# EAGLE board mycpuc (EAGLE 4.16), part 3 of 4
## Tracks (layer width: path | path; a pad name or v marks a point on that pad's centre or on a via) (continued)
GND  (via drill 0.3 pad 0.76, 0.3 pad 0.81) (continued)
  Top 0.203: LED3.C 85.96,2.92 85.95,2.91 85.95,1.91 | LED4.C 81.96,1.92 81.95,1.91 | LED5.C 78.01,1.92 78,1.91 | LED6.C 74.01,1.92 74,1.91 | IC7.22 20.06,47.7 19.25,48.51 18.65,48.51 v18.05,49.11 | 92.93,41.16 92.3,41.16 92.15,41.31 90,41.31 89.55,41.76 87.05,41.76 | IC8.22 22.39,58.72 22.55,58.56 27.4,58.56 28.15,59.31 28.15,60.36 27.85,60.66 27.05,60.66 26.5,61.21 25.95,61.21 25.55,61.61 C63.2
  Top 0.254: LED10.C 55.01,2.1 55.2,1.91 | LED7.C 67.01,1.92 67,1.91 | LED8.C 63.01,1.92 63,1.91 | LED9.C 59.01,1.92 59,1.91 | 15.8,20.53 IC6.11 | IC6.12 15,19.86 15.8,19.86 | 10.4,58.91 10.4,58.9 J1.C20 | IC6.13 20.85,19.76 | IC9.2 16.93,37.34 18,38.41 | 18,38.41 v18,38.46 | IC9.22 19.72,36.69 18,38.41 | IC9.11 15.87,31.49 16,31.36 16,30.84 | 16,41.85 16,42.31 15.81,42.5 IC7.11 | IC7.2 16.09,48.35 16.85,49.11 v18.05,49.11 | 120.45,13.11 120.47,13.09 IC19.8 | IC19.13 115.39,17.62 117,16.01 119.4,16.01 120.45,14.96 v120.45,14.71 | 104.85,14.96 v104.8,15.31 104,16.11 103.1,16.11 102.55,15.56 102.55,14.66 102.95,14.26 102.95,12.96 102.94,12.97 IC18.6 | IC20.13 81.33,17.18 83.75,14.76 v85.85,14.76 | 15.05,59.36 15.04,59.37 IC8.2 | 115.55,28.86 115.56,28.85 C76.2 | R60.2 122.92,15.83 v121.8,14.71 | v139.45,80.16 139.4,80.16 | v139.45,80.16 IC13.12 | v139.45,80.16 139.45,80.21 140.15,79.51 IC13.11 | IC13.13 v136.45,80.16 | IC13.22 137.05,74.31 139.1,72.26 139.1,72.06 139.15,72.01 v139.15,72.06 | IC21.P142 62.25,52.91 62.8,52.36 v62.8,52.41 63.3,52.41 63.75,52.86 IC21.P139 | v65.1,50.96 65.05,50.96 65.1,51.16 65.1,52.66 65.25,52.81 IC21.P136 | IC21.P117 74.75,52.11 v75.75,51.11 76.1,51.11 76.6,51.61 76.6,52.76 76.25,53.11 IC21.P114 | IC21.P9 v60.59,47.75 v60.6,47.76 | IC21.P16 v60.59,44.25 v60.6,44.26 | v60.6,41.26 60.6,41.31 60.54,41.25 IC21.P22 | IC21.P29 v60.59,37.75 v60.6,37.76 | v79.4,38.26 79.4,38.31 79.46,38.25 IC21.P81 | v79.4,41.76 79.35,41.76 79.36,41.75 IC21.P88 87.05,41.76 | IC21.P101 v79.41,48.25 v79.4,48.26 | IC21.P94 v79.41,44.75 v79.4,44.76 | IC21.P39 62.25,33.76 v62,34.01 | 61.75,33.76 IC21.P38
  Top 0.254: v62,34.01 61.75,33.76 | 61.25,33.76 IC21.P37 | 61.75,33.76 61.25,33.76 | IC21.P45 65.25,34.96 v65.3,35.01 65.25,35.06 | IC21.P42 63.75,33.01 62.75,34.01 v62,34.01 | v74.8,35.06 74.8,35.01 74.75,34.96 IC21.P64 | IC21.P67 76.25,32.86 77.4,34.01 v77.55,34.01 | 61.25,33.76 v60.85,33.76 | 87.05,41.76 87.1,41.76 IC14.22 87.07,41.76 87.05,41.76 | IC14.11 92.32,46.99 92.05,47.26 92.05,47.64 | 92.93,41.16 IC14.2 | J3.1 138.81,86.1 138.75,86.16 | 133.8,87.66 133.76,87.7 SW2.2 | 147.6,49.8 J5.15 147.62,49.88 | 106.85,97.06 106.86,97.05 LED1.C 106.96,97.05 107,97.01 108.5,97.01 | v107,93.26 106.95,93.31 107.8,93.31 108.5,94.01 108.5,97.01 | 108.5,97.01 109.8,98.31 113.3,98.31 v114.55,97.06 114.55,97.01 114.6,97.06 LED11.C | C16.- 78.36,72.26 78.35,72.41 78.61,72.43 R113.1 | 88.08,61.61 88.1,61.61 C12.2 | 147.62,49.88 147.65,49.91 | R119.2 145.45,47.71 147.62,49.88 | R118.2 144.17,54.03 143.8,53.66 143.8,50.41 144.25,49.96 C73.2 | R132.2 v136.14,19.5 v136.15,19.51 | v118.8,59.66 118.8,59.71 118.85,59.66 | v118.8,56.61 118.8,56.66 | 115.25,47.41 v115.2,47.46 | 109.25,47.41 v109.4,47.46 | 105.8,49.66 v106.1,49.91 | IC23.100 106.53,60.99 106.5,60.91 | v114.55,59.91 114.53,59.93 | v118.8,53.16
  Top 0.3: IC8.2 11.76,59.37 11.3,58.91 10.45,58.91 10.4,58.91
  Top 0.305: 16,52.87 16,53.36 15.84,53.52 IC8.11 | IC5.10 83.25,70.36 v82.9,70.41 82.7,70.41 82.6,70.31 IC5.11 IC5.15 | 81.95,63.31 IC5.3 | 81.95,64.06 81.95,64.56 82.6,65.21 | C73.2 147.5,49.96 147.62,49.84 J5.15 147.62,49.79 147.65,49.76 147.6,49.71 147.6,47.41 C74.2 | 118.85,59.66 IC23.75 | 118.8,56.66 IC23.69 | v118.8,53.16 IC23.62 | IC23.44 115.53,47.14 115.25,47.41 | IC23.31 109.03,47.18 109.25,47.41 | IC23.21 105.8,49.66 | v107.3,59.66 106.5,60.46 106.5,60.91 | 114.53,59.93 IC23.84
  Top 0.406: 55.2,1.91 57,1.91 | 57,1.91 59,1.91 63,1.91 67,1.91 74,1.91 78,1.91 81.95,1.91 85.95,1.91 | 15.8,20.53 15.8,19.86 15.8,19.11 15.1,18.41 15.1,16.11 v15.05,16.11 | 70.7,14.76 70.68,14.78 C88.2 | 57.3,18.51 57.3,19.64 Q2.2 | 50.21,18.82 v50.25,18.86 | 18,28.86 v18,27.51 | v18,30.21 18,28.86 | 18,28.86 C54.2 | 18,28.86 C53.2 | 20.85,19.76 20.85,19.21 v20.5,18.86 | v18,38.46 18,39.91 | 18,39.91 v18,41.31 18,41.36 | 18,39.91 C59.2 | 18,39.91 C60.2 | IC9.12 16,30.84 17.37,30.84 v18,30.21 | v18,30.21 18,30.26 18.58,30.84 IC9.13 | IC7.12 16,41.85 16.01,41.85 16.5,41.36 18,41.36 | IC7.13 19.99,41.85 19.5,41.36 18,41.36 | v18.05,49.11 18.05,50.91 | 18.05,50.91 v18.05,52.31 | 18.05,50.91 C55.2 | 18.05,50.91 C56.2 | IC8.12 16,52.87 17.49,52.87 v18.05,52.31 | v18.05,52.31 18.05,52.36 18.56,52.87 IC8.13 | C92.2 75.81,16.75 75.85,16.71 75.75,16.61 v75.75,15.31 | C90.2 95.52,15.84 96.6,14.76 v96.75,14.76 96.7,14.76 96.6,14.66 96.6,13.11 96.58,13.09 IC18.1 | v109.7,15.21 109.5,15.41 109.5,16.51 109.49,16.52 C91.2 | v104.8,15.31 104.8,14.76 105.45,14.11 105.45,13.01 IC18.8 | IC20.8 86.41,14.71 86.45,14.76 v85.85,14.76 v86.8,14.76 | 115.55,30.26 v115,30.26 | 115.55,30.26 v116,30.26 | 115.55,28.86 115.55,30.26 | C76.2 115.55,28.63 115.55,28.46 113.7,28.46 C79.2 | 57,1.91 v57,2.81 | C84.2 85.45,10.06 v85.1,9.71 | IC14.13 89.02,47.64 v89.15,47.61 | IC14.12 92.05,47.64 92.03,47.64 v92,47.61 | C72.2 90.88,37.78 v91.3,37.38 91.42,37.31 91.66,37.08 C93.2 | 138.75,86.16 138.75,86.81 137.9,87.66 133.8,87.66 | R13.1 54.33,85.48 53.2,86.61 50.8,86.61 50.8,86.6 C6.- | 67.98,87.03 67.95,87.06 67.99,87.1 R11.1 67.97,87.18 67.95,87.16
  Top 0.406: v67.45,80.46 v68.4,80.46 68.4,81.46 67.65,82.41 67.6,82.36 66.5,81.46 v66.5,80.46 v67.45,80.46 | v67.45,80.46 67.45,82.16 | IC5.15 82.6,65.21 82.22,64.78 C11.2 | 80.9,63.61 80.9,66.91 84.3,66.91 84.3,63.61 80.9,63.61 | 80.9,63.61 81.95,63.61 81.95,63.31 | J1.A1 | IC11.10 29.59,94.02 v29.57,94.01 | v31,88.61 31.02,88.61 30.86,88.44 IC11.28 | IC10.10 29.49,80.47 29.49,80.45 29.45,80.41 29.45,79.71 28.98,79.23 v28.98,78.61 | v31.38,72.83 31.35,72.63 30.86,72.14 IC10.28 | 25.53,61.58 | C63.2 25.53,61.58 | 25.53,61.58 C64.2 | 25.53,61.58 25.55,61.56 | 36.9,29.31 37,29.31 38.35,30.66 39.6,30.66 v39.7,30.56
  Top 0.6: C63.2 25.78,62.59 26.25,63.06 v26.3,63.06
  Top 0.61: v72.15,14.76 70.7,14.76 | Q1.2 65.25,19.71 66.25,20.71 v67.75,20.71 | 57.3,18.51 58.42,18.51 v59.23,17.71 | C89.2 50.21,18.82 | 120.45,13.11 v120.45,14.71 v121.8,14.71 | v76.4,70.71 76.4,71.06 | v82.9,70.41 82.95,65.06 81.95,64.06 81.95,63.31 | v23.1,30.46 28.8,30.46 29.95,29.31 36.9,29.31
  Top 0.813: 46.55,86.86 J4.59 | C6.- 50.47,86.86 46.55,86.86 | 67.98,87.03 C7.2 67.98,82.74 67.6,82.36 67.64,82.31 C2.- | C5.2 60.1,87.21 60.1,88.25 60.64,88.8 60.65,88.81 67.35,88.81 67.95,88.21 67.95,87.16 | 75.2,87.81 v75.9,87.81 75.9,82.96 75.2,82.96 75.2,87.81 | 74,87.81 v73.8,87.81 73.45,87.81 | 74,87.81 74.75,87.81 | 74.75,87.81 v74.85,87.81 | 73.45,87.81 v72.7,87.81 72.7,86.91 | 73.45,87.81 73.44,87.79 C15.- 73.42,85.83 73,85.36 | 73,82.86 72.42,82.33 C14.- 72.42,82.43 72.55,82.56 72.77,82.34 C13.- | v75.45,70.71 v76.4,70.71 | v82.9,70.41 v83.8,70.41 | 74.75,87.81 75.2,87.81 | 74.75,87.81 74.75,82.96 74,82.96 | 74,82.96 73.95,83.21 | 74,87.81 74,82.96 | 44,86.86 46.55,86.86 | 10.4,13.21 10.4,13.2 J1.C2 | 14.87,13.21 C17.- | 10.4,89.38 10.4,89.41 | 7.45,89.38 7.45,89.36 | C18.- | v100.95,28.06 100.95,28.46 100.96,28.47 | v100.95,27.06 v100.95,28.06 | v100.95,28.06 v100.95,29.06
  Top 1.016: 76.4,71.06 77,71.66 77.7,71.66 78.36,72.31 C16.- | C10.- 88.07,58.88 88.1,58.91 88.08,58.93 88.08,61.61 C9.- 82.83,64.53 82.85,64.61 82.75,65.41 IC5.15 | 10.4,13.21 14.87,13.21 | J1.A1 5.35,13.21 10.45,13.21 10.45,10.66 J1.A1
  Top 1.27: J1.A32 7.45,89.38 | 7.45,89.38 10.4,89.38 | 7.45,89.38 C18.- | 100.96,28.47 100.97,28.46 102.85,28.46 D20.A | v38.75,10.81 38.12,10.11 39.48,10.11 38.75,9.21 D21.A | v38.75,10.81 v39.75,10.81 | v38.75,10.81 v37.75,10.81 | J1.A20 10.45,58.91
  Top 1.676: 73,82.86 73,85.36
  Route2 0.406: 65.1,93.71 65.1,89.91 | 65.1,93.71 65.1,94.61 | 63.5,99.21 66.75,99.21 | 65.1,93.71 62.3,93.71 61.65,93.06 59.25,93.06 58.05,94.26
  Route2 1.93: 43.75,58.91 47.05,58.91
  Bottom 0.203: T5.2 122.05,83.06 122.05,83.76 122.3,84.01 124.9,84.01 | T2.2 134.05,83.76 133.8,84.01 130.1,84.01 | v31.38,72.83 31.4,72.81 31.47,72.88 31.32,72.88 | v28.98,78.61 29,78.61 28.92,78.64 28.93,78.59 | v29.57,94.01 29.6,94.01 29.62,93.98 29.57,93.98
  Bottom 0.254: 10.45,58.91 10.45,58.9 J1.C20 | v115,30.26 115,30.21 114.91,30.3 | C81.2 89.46,15.47 89.45,15.46 89.4,15.51 | v85.85,14.76 v86.8,14.76 | R66.2 68.4,12 68.4,12.86 69.05,13.51 70.9,13.51 v72.15,14.76 | 53.89,21.87 v53.85,21.96 | 54,15.01 53.95,15.06 | T2.2 | T4.2 130.04,84.01 130.1,84.01 129.45,84.66 v129.45,86.66 | T3.2 126.05,83.76 125.8,84.01 124.9,84.01 v124.9,86.66 | v129.5,94.21 129.5,94.16 129.07,94.59 IC2.1 | v114.55,97.06 114.5,97.06 v114.56,97.05 C1.2 | v107,93.26 106.9,93.21 106.98,93.29 | 14.49,71.52 R24.1 14.47,69.19 14.48,69.18 | 14.49,71.52 R25.1 14.49,73.77 14.5,73.76 14.51,73.77 R26.1 14.51,76.02 14.5,76.01 14.48,76.03 R27.1 14.48,80.04 14.5,80.11 v14.5,80.06 13.85,80.06 13,80.91 C52.2 | 14.49,71.52 14.5,71.51 | 14.48,69.18 14.5,69.16 | 14.48,69.18 R22.1 14.48,66.94 | 14.48,66.94 14.5,66.96 R23.1 14.5,64.71 14.51,64.72 R21.1 14.51,62.55 14.53,62.53 | 14.48,66.94 14.45,66.91 | 14.53,62.53 14.55,62.51 | R17.2 14.53,62.53 | 14.55,62.56 14.55,62.41 14.85,62.11 15.35,62.11 v16.15,61.36 | v15.05,95.01 14.5,95.01 13.65,94.16 R39.2 | C8.2 82.89,66.75 82.9,67.21 v82.9,70.41 | T1.2 41.72,89.89 44,87.56 44,86.76 44.01,86.77 J4.60 | IC12.47 35.88,66.08 v35.65,66.31 35.38,66.14 IC12.46 | IC12.27 25.88,63.48 v26.3,63.06 | R114.2 41.38,55.89 41.65,56.16 41.65,57.06 43.5,58.91 43.95,58.91 43.96,58.9 J4.38 | 116.9,34.01 116.89,34.32 C75.2 | 58.05,94.26 J2.3 | 107.4,76.26 107.42,76.28 J15.16
  Bottom 0.305: v109.53,54.28 109.55,54.33 108.84,54.31 C100.1 | D26.C 106.57,85.69 108.7,83.56 108.7,77.46 107.5,76.26 107.48,76.28 J15.16
  Bottom 0.35: IC16.25 89.6,9.8 89.67,9.81 91.05,9.81 v91.35,9.51
  Bottom 0.406: 10.45,58.91 11.3,58.91 11.95,58.26 12.6,58.26 | 12.6,58.26 C57.2 | C58.2 17.65,58.21 17.6,58.26 12.6,58.26 | 114.91,30.3 IC15.25 | v115,30.26 v116,30.26 116,30.41 116.9,31.31 116.9,34.01 | 89.4,15.51 87.55,15.51 v86.8,14.76 87.83,13.73 C80.2 | v140.4,68.31 140.15,68.06 139.05,68.06 139.03,68.04 C70.2 | v139.15,72.06 139.15,72.01 139.17,71.99 C69.2 139.15,70.46 139.2,70.46 139.2,69.36 138.95,69.11 138.95,68.11 | C41.2 69.45,48.61 69.42,48.64 | C45.2 | 72.89,48.62 C40.2 | C36.2 77,49.36 77.02,49.34 | C37.2 63.67,47.54 63.64,47.57 | 69.65,37.46 69.67,37.44 C43.2 | 71.43,37.43 71.45,37.41 | 71.43,37.43 C39.2 | C39.2 71.43,37.43 | C44.2 73.15,37.46 73.14,37.45 | 64.11,36.57 64.1,36.56 | 64.11,36.57 C34.2 | 64.14,36.6 64.11,36.57 | 77.25,36.56 76.97,36.58 C32.2 | 77.25,38.26 C31.2 | 72.65,38.81 v72.6,38.86 | 63.6,50.96 v65.1,50.96 | 62.9,52.36 62.95,52.41 v62.8,52.41 62.91,52.52 | 77.55,36.41 77.3,36.66 | v65.3,35.01 64.9,35.01 64.25,35.66 | v62,34.01 62.05,34.01 62.05,34.06 | C50.2 | C3.2 69.55,45.31 69.5,45.36 | C20.2 72.44,54.35 73,54.91 v73,55.61 73,55.66 | C27.2 60.95,54.41 | C27.2 | 61.14,54.22 C27.2 | 77.21,54.15 77.2,54.16 77.22,54.18 C21.2 77.25,54.16 77.6,53.81 | C33.2 64.14,38.45 64.15,38.46 | 61,38.46 61,40.86 | 79.39,45.12 79.4,45.11 | C22.2 77.4,31.66 | C22.2 77.55,31.81 | 78.92,31.78 C30.2 | C22.2 77.55,31.81 | 77.55,31.81 77.7,31.81 77.7,31.78 | 77.55,34.06 v77.55,34.01 | C23.2 66.94,30.17 v66.95,30.11 | 54,17.06 C47.2 | 54,17.06 54.04,17.1 C49.2 53.9,19.01 53.9,21.86 53.89,21.87 | C48.2 53.95,15.06 54,15.11 54,17.06 | 54.8,12.31 v54.75,12.36 54,13.11 54,15.01 | v61.85,11.01 61.85,11.06 62.55,11.06 63.94,12.45 IC1.11
  Bottom 0.406: v89.15,47.61 89.85,47.61 | C71.2 89.85,43.71 89.85,47.61 | 89.85,47.61 v92,47.61 | 146.3,96.66 146.29,96.67 C87.2 | C85.2 106.67,93.59 107.05,93.21 106.98,93.29 | 50.31,87.17 50.3,87.16 | IC4.1 50.31,87.17 | 50.31,87.17 50.34,87.2 | v107.3,59.66 107.5,59.66 107.95,59.21 107.95,58.26 C95.1 | C96.1 114.42,58.51 114.55,58.58 v114.55,59.91 | C97.1 117.1,52.91 117.35,53.16 v118.8,53.16 | C101.1 116.95,48.01 116.69,47.88 115.17,47.88 v115.2,47.46 115.15,47.56 115.15,48.81 114.9,49.16 C98.1 | C99.1 108.92,46.81 109.38,47.26 109.38,47.44 v109.4,47.46 | Q3.GND 120.72,61.49 120.7,61.46 | 120.7,61.46 v120.7,60.81 | 120.7,61.46 120.36,61.77 IC24.4 118.81,61.77 118.8,61.76 | C103.1 116.33,62.88 117.45,61.76 118.8,61.76 | v118.8,59.66 118.8,61.76 | v29.57,94.01 29.57,93.98 29.25,93.71 C65.2 | v31,88.61 30.95,88.63 31.55,89.23 C66.2 | C67.2 27.95,77.31 27.95,78.21 28.33,78.59 28.93,78.59 | 31.32,72.88 31.32,72.89 31.35,72.81 31.07,73.09 31.07,74.89 31.65,75.31 C68.2
  Bottom 0.61: C46.2 69.42,48.64 | C41.2 C45.2 | C45.2 72.89,48.62 | C35.2 77.02,49.34 | 63.64,47.57 C38.2 | C42.2 69.65,37.46 | C43.2 C39.2 | C39.2 73.14,37.45 | C33.2 64.14,36.6 | 77.25,36.56 77.25,38.26 78.55,38.26 | 67.6,48.61 v67.6,47.26 v68.85,47.26 69.5,46.61 69.5,45.36 | v72.6,47.26 72.6,48.61 | 67.65,37.46 v67.65,38.86 | 72.65,37.46 72.65,38.81 | 63.6,49.21 63.6,50.96 | 62.9,52.36 62.9,51.61 63.65,50.86 | v60.6,47.76 63.7,47.76 | v75.75,51.11 76.25,51.11 77,50.36 77,49.41 | v79.4,48.26 79,48.26 78.35,47.61 | 78.35,47.61 77,47.61 | 78.35,47.61 79.4,46.56 79.4,45.11 v79.4,44.76 | 77.55,36.41 77.55,34.06 77.55,31.81 | 78.55,38.26 79.35,38.26 | v79.4,41.76 78.55,40.91 78.55,38.26 | 64.25,36.46 64.25,35.66 63.85,35.26 63.25,35.26 62.05,34.06 | v60.6,37.76 60.6,38.06 61,38.46 64.15,38.46 | 60.8,33.76 61.1,34.01 v62,34.01 62.31,33.7 C24.2 | v67.65,38.86 C50.2 | v67.65,38.86 v68.85,38.86 | 61.14,54.22 C19.2 62.91,52.52 | 77.21,54.15 C28.2 | 77.6,53.81 77.6,52.61 v77.8,52.41 | C26.2 61,40.86 v60.6,41.26 | C29.2 79.39,45.12 | 77.7,31.78 78.92,31.78 | C25.2 60.47,33.38 v60.85,33.76 | J9.4 146.3,96.66 | 67.5,80.51 v67.45,80.46 67.4,80.41 67.95,80.41 67.95,71.81 | 67.95,71.81 67.93,71.83 C61.2 67.62,71.83 67.65,71.86 67.7,71.81 67.95,71.81 | 67.95,71.81 C62.2 | C104.2 56.98,95.33 J2.3
  Bottom 0.813: 50.34,87.2 C4.2 | J4.59 46.55,86.86 | 49.91,86.86 IC4.1 | v68.4,80.46 v66.5,80.46
  Bottom 1.27: 46.55,86.86 49.91,86.86 | J15.18 104.9,76.3 104.9,76.31 107.45,76.31
  other vias: 75.85,67.31 79.65,64.91 77.6,67.31 69.2,71.76
  pour Route2 (isolate 0.254): 0.35,99.71 0.35,0.31 159.75,0.31 159.75,99.71 65.3,99.71 65.3,66.51 56.05,66.51 49.55,73.06 49.55,89.86 64.9,89.86 64.9,99.71
  pour Bottom (isolate 0.254): 62.95,55.66 80.25,55.66 80.9,55.01 80.9,31.76 80.25,31.11 77.25,31.11 75.25,33.11 64.8,33.11 62.8,31.11 60.15,31.11 59.35,31.91 59.35,54.46 59.65,54.76 62.05,54.76
  pour Top (isolate 0.305, no thermals): 80.95,63.11 86.95,63.11 86.95,57.66 89.25,57.66 89.25,67.26 83.25,67.26 83.25,67.81 75.4,67.81 75.4,63.61 80.45,63.61
  pour Bottom: 69.55,82.01 65.45,82.01 65.45,68.36 72.4,68.36 72.4,73.21 71.2,74.41 71.2,80.36
  pour Top (no thermals): 66.25,83.41 66.25,86.56 58.3,86.56 58.3,90.31 68.85,90.31 68.85,83.41
IN0
  Top 0.254: IC18.2 97.9,12.91 98,12.9 98,11.9 100.35,9.56 101.7,9.56 103.15,8.11 103.12,7.78 J10.4
  Bottom 0.203: 103.05,9.71 R95.2
  Bottom 0.254: J10.4 103.12,9.64 R95.2
IN1
  Top 0.254: IC18.3 99.12,11.78 100.75,10.16 103.35,10.16 105.7,7.81 105.69,7.8 J10.6
  Bottom 0.203: R96.2 105.66,9.7 105.65,9.71
  Bottom 0.254: J10.6 105.66,9.7
IN2
  Top 0.254: IC18.4 100.39,11.76 101.4,10.76 105.25,10.76 J10.8
  Bottom 0.203: 108.2,9.66 R97.2
  Bottom 0.254: R97.2 | J10.8 108.2,9.66
IN3
  Top 0.254: IC18.5 101.67,11.74 102.05,11.36 106.45,11.36 110.04,7.77 | 110.04,7.77 110.75,7.76 | 110.04,7.77 J10.10
  Bottom 0.203: R98.2 110.74,9.7 110.75,9.71
  Bottom 0.254: J10.10 110.74,9.7
IN4
  Top 0.254: IC18.10 104.2,17 104.9,16.31 105.45,16.31 105.75,16.01 105.75,14.96 106.45,14.26 106.45,12.31 109.25,9.51 111.55,9.51 113.28,7.78 | 113.28,7.78 113.3,7.76 | 113.28,7.78 J10.12
  Bottom 0.203: R99.2
  Bottom 0.254: J10.12 113.28,9.63 R99.2
IN5
  Top 0.254: IC18.11 102.94,20.44 103.15,20.66 106.2,20.66 106.5,20.36 106.5,15.16 107.15,14.51 107.15,12.56 109.5,10.16 113.5,10.16 115.85,7.81 115.84,7.8 J10.14
  Bottom 0.203: R100.2 115.79,9.7 115.8,9.71 115.82,9.69
  Bottom 0.254: J10.14 115.82,9.69
IN6
  Top 0.254: IC18.12 101.67,20.47 102.45,21.26 106.65,21.26 107.15,20.76 107.15,15.51 107.85,14.81 107.85,12.86 109.9,10.76 115.45,10.76 118.4,7.81 118.39,7.8 J10.16
  Bottom 0.203: 118.36,9.65 R101.2
  Bottom 0.254: 118.36,9.65 118.4,9.61 118.36,9.57 J10.16
IN7
  Top 0.254: IC18.14 99.12,20.53 100.45,21.86 106.95,21.86 107.85,20.96 107.85,15.76 108.55,15.06 108.55,13.11 110.25,11.36 117.35,11.36 J10.18 | J10.18 120.95,7.76 | J10.18
  Bottom 0.203: R102.2
  Bottom 0.254: R102.2 120.9,9.61 J10.18
INTRES  (via drill 0.3 pad 0.76)
  Top 0.203: J4.54 43.99,79.22
  Top 0.254: J4.54 44.04,79.22 45.25,78.01 47.4,78.01 48.15,77.26 48.15,71.46 51.05,68.56 64.45,68.56 73.75,59.26 IC21.P119 | 43.99,79.22 42.65,80.56 42.65,91.11 v42.1,91.66
  Bottom 0.203: 42.15,91.66 v42.1,91.66 40.9,91.66 40.69,91.65 T1.1
  Bottom 0.254: T1.1 40.59,91.87 40.55,91.91 40.58,91.94 R115.1
INTRQ
  Top 0.254: J12.31 136.21,55.07 137.45,56.31 139.85,56.31 141,55.16 | 141,55.16 J13.31 | 141,55.16 142.8,55.16 143.55,55.91 145.5,55.91 145.48,55.93 R118.1
IO_LOAD
  Top 0.254: IC21.P97 85.04,46.25 85.15,46.36 87.1,46.36 IC14.15
IO_OUT1
  Top 0.254: IC21.P96 83.01,45.75 83.05,45.71 87.08,45.71 IC14.16
IO_OUT2
  Top 0.254: IC21.P95 82.96,45.25 83.15,45.06 87.1,45.06 IC14.17
IOCLK  (via drill 0.3 pad 0.81)
  Top 0.203: IC14.10 92.12,46.34 90.7,47.76 v90.7,48.56
  Top 0.254: v103.55,15.11 103.55,14.86 103.5,14.81 104.2,14.1 IC18.7 | IC19.11 117.92,17.28 v117.95,17.26 | IC20.11 83.9,19 v83.9,17.21
  Route15 0.254: v91.05,33.01 91.05,33.31 92.9,35.16 92.9,37.81 90.62,40.11 90.62,43.86 89.88,44.61 89.88,47.73 v90.7,48.56
  Bottom 0.254: v117.95,17.26 116.95,16.26 113.7,16.26 113.05,16.91 111.9,16.91 111.3,16.31 104.4,16.31 103.55,15.46 v103.55,15.11 103.55,15.06 102.35,13.86 96.35,13.86 93,17.21 87.95,17.21 86.85,16.11 84.8,16.11 83.9,17.01 v83.9,17.21 75.9,17.21 72.6,20.51 72.6,23.21 74.7,25.31 83,25.31 85,27.31 85.9,27.31 91,32.41 91,33.01 v91.05,33.01
IOEN1
  Top 0.254: IC9.3 12.47,36.69 11.85,37.31 4.35,37.31 3.9,37.76 3.9,74.81 4.5,75.41 7.05,75.41 8.3,76.66 10.4,76.66 10.42,76.68 J1.C27
IOEN2
  Top 0.203: 12.53,36.04 11.5,35.01 4.25,35.01 3.15,36.11
  Top 0.254: 12.53,36.04 IC9.4 | 3.15,36.11 3.15,75.51 4.4,76.71 5.3,76.71 5.32,76.68 J1.A27
IOEN3
  Top 0.203: 12.83,35.39 12,34.56 3.52,34.56 2.4,35.68
  Top 0.254: 12.83,35.39 IC9.5 | J1.A28 5.34,79.17 4.12,79.16 2.38,77.41 2.4,35.68
IOIN  (via drill 0.3 pad 0.81)
  Top 0.254: IC21.P98 84.14,46.75 v84.45,47.06 | v93.6,23.96 93.6,24.01 93.3,24.31 93.3,28.21 89.15,32.36 v89.15,33.01 | v73.85,64.26 73.45,64.26 65.65,72.06 55.15,72.06 53.55,73.66 v49.85,73.66
  Route15 0.254: v98.45,24.01 v98.45,17.21
  Bottom 0.203: 27.4,56.81 23.1,61.11 20.85,61.11 19.49,62.47
  Bottom 0.254: R111.1 98.52,17.21 v98.45,17.21 | v89.15,33.01 86.95,35.21 86.95,41.16 84.45,43.66 v84.45,47.06 83.95,47.56 83.95,62.11 82,64.06 74.05,64.06 v73.85,64.26 | v98.45,24.01 98.45,24.06 98.35,23.96 v93.6,23.96 | v49.85,73.66 51.15,73.66 52.55,72.26 52.55,69.61 50.25,67.31 50.25,60.46 47.4,57.61 43.25,57.61 42.55,56.91 42.55,55.11 41.75,54.31 37.7,54.31 35.2,56.81 27.4,56.81 | D1.2 19.49,62.47
IOLOAD  (via drill 0.3 pad 0.81)
  Top 0.203: v90.8,46.51 91.05,46.51 91.82,45.74 93.42,45.74 93.45,45.71 IC14.9
  Top 0.254: IC19.12 116.66,20.4 116.45,20.61 109.15,20.61 107.25,22.51 102,22.51 | 102,22.51 99.9,22.51 97.9,20.51 97.9,19.21 97.85,19.16 97.86,19.15 IC18.15 97.86,18.01 97.55,17.71 97.55,16.61 v97,16.06 | IC20.12 82.59,17.11 83.4,16.31 85.75,16.31 v86.45,17.01 | 102,22.51 v102,24.01
  Route15 0.254: v90.8,46.51 91.2,46.51 95.33,42.38 95.33,34.83 v93.5,33.01
  Bottom 0.254: v97,16.06 95.3,16.06 93.5,17.86 87.25,17.86 86.5,17.11 86.5,17.01 86.45,17.06 v86.45,17.01 | v102,24.01 99.5,26.51 99.5,28.56 98.9,29.16 98.1,29.16 94.25,33.01 v93.5,33.01
IOOUT1  (via drill 0.3 pad 0.81)
  Top 0.203: IC14.8 92.27,45.04 92.1,45.21 91.5,45.21 91.35,45.36 v90.8,45.36
  Top 0.254: IC19.14 114.11,17.26 v114.15,17.26 | v124,15.01 124.45,15.46 124.45,22.26 119.6,27.11 119.6,30.06 114.55,35.11 108.8,35.11 v108.7,35.16
  Bottom 0.254: v124,15.01 123.95,15.01 120.55,18.41 117.05,18.41 115.9,17.26 v114.15,17.26 | v108.7,35.16 108.7,35.11 105.85,32.26 99.65,32.26 96.05,35.86 96.05,41.36 92.05,45.36 v90.8,45.36
IOOUT2  (via drill 0.3 pad 0.81)
  Top 0.254: IC20.14 80.06,20.2 79.25,21.01 v75,21.01 | IC14.7 91.57,44.39 v91.6,44.41
  Route15 0.254: v92.25,33.01 92.25,32.98 92.28,33.23 93.55,34.48 93.55,42.83 91.95,44.41 v91.6,44.41
  Bottom 0.254: v75,21.01 73.95,21.01 73.35,21.61 73.35,22.91 75.15,24.71 83.35,24.71 85.3,26.66 86.25,26.66 92.25,32.66 v92.25,33.01
IORD  (via drill 0.3 pad 0.81)
  Top 0.254: IC21.P113 76.75,55.51 75.9,56.36 75.9,59.91 65.15,70.66 54.55,70.66 52.75,72.46 51.15,72.46 50.75,72.06 50.75,70.96 51.4,70.31 v51.65,70.31
  Bottom 0.254: J4.40 45.3,60.16 47.1,60.16 49.5,62.56 49.5,68.16 v51.65,70.31
IORDY
  Top 0.254: 130.9,48.76 126,48.76 124.6,50.16 IC23.56 | 130.9,48.76 130.9,50.01 | IC23.56 120.5,50.16 | IC23.56 | J13.27 139.69,48.76 130.9,48.76 | 130.9,50.01 J12.27 | R120.1 130.93,50.04 130.9,50.01
IOWR
  Top 0.254: R94.2 77.39,58.02 77.4,58.01 77.25,57.86 IC21.P112
IOWR_R  (via drill 0.3 pad 0.81)
  Top 0.254: R94.1 77.39,60.82 77,61.21 75.55,61.21 65.4,71.36 54.85,71.36 53.15,73.06 50.65,73.06 v49.85,72.26
  Bottom 0.254: v49.85,72.26 48,70.41 48,63.51 47.15,62.66 45.95,62.66 44.65,63.96 J4.42
IRQ  (via drill 0.3 pad 0.81)
  Top 0.254: R36.2 16.55,62.51 17.05,62.01 v17.35,62.01 | IC21.P130 68.25,56.86 64.05,61.06 52.65,61.06 v51.3,62.41
  Route2 0.254: v16.65,82.91 15.95,82.21 15.95,63.41 v17.35,62.01
  Bottom 0.203: 19.7,61.06 20.2,60.56 22.8,60.56 27.25,56.06
  Bottom 0.254: v51.3,62.41 51.3,56.41 47.35,52.46 38.35,52.46 34.75,56.06 27.25,56.06 | v17.35,62.01 18.3,61.06 19.7,61.06 | D6.1 17.93,82.83 17.85,82.91 v16.65,82.91
IRQ1
  Top 0.254: R29.1 11.75,64.71 11.15,65.31 8.2,65.31 7,66.51 5.3,66.51 5.32,66.52 J1.A23
  Bottom 0.254: R21.2 11.67,64.74 11.15,65.26 8.25,65.26 7,66.51 5.35,66.51 J1.A23
IRQ2
  Top 0.254: J1.C24 10.44,69.06 10.45,69.06 10.45,68.51 11.95,67.01 R30.1
  Bottom 0.254: J1.C24 10.58,69.24 R22.2
IRQ3
  Top 0.254: R31.1 12.2,69.26 11.15,70.31 8.25,70.31 7,69.06 5.3,69.06 5.31,69.06 J1.A24
  Bottom 0.254: R23.2 12.65,67.01 12.42,67.24 11.62,67.24 11.1,67.76 8.3,67.76 7,69.06 5.3,69.06 5.31,69.06 J1.A24
IRQ4
  Top 0.254: 10.4,71.6 10.35,71.66 | 10.4,71.6 J1.C25 | R32.1 10.5,71.51 10.4,71.6
  Bottom 0.254: 10.4,71.6 10.35,71.66 | J1.C25 10.4,71.6 | R24.2 10.47,71.54 10.4,71.6
IRQ5
  Top 0.254: R33.1 11.95,73.76 11.1,72.91 8.35,72.91 7.05,71.61 5.3,71.61 5.3,71.6 J1.A25
  Bottom 0.254: R25.2 12.59,73.75 12.25,73.41 11.63,73.39 11.15,72.91 8.35,72.91 7.05,71.61 5.3,71.61 5.3,71.6 J1.A25
IRQ6
  Top 0.254: R34.1 12.95,76.01 11.05,74.11 10.5,74.11 10.45,74.16 10.44,74.14 J1.C26
  Bottom 0.254: R26.2 12.28,75.64 12.15,75.71 11.7,75.71 10.45,74.46 10.45,74.16 10.44,74.14 J1.C26
IRQ7
  Top 0.254: R35.1 12.45,78.26 12.05,77.86 12.05,76.41 11.1,75.46 8.3,75.46 7,74.16 5.3,74.16 5.31,74.14 J1.A26
  Bottom 0.254: R27.2 12.58,77.96 11.4,77.96 9.85,77.96 8.3,76.41 8.3,75.46 7,74.16 5.3,74.16 5.31,74.14 J1.A26
IRQIN  (via drill 0.3 pad 0.79)
  Top 0.254: v9.5,62.71 12.7,62.71 R36.1
  Bottom 0.254: 9.43,62.68 9.65,62.68 v9.5,62.71 | 9.43,62.68 v9.5,62.71 | v9.5,62.71 12.45,62.71 12.57,62.63 R17.1 | 9.43,62.68 9.45,62.71 6.75,60.01 6.75,39.76 10.45,36.06 10.44,36.04 J1.C11
IRQS1  (via drill 0.3 pad 0.81)
  Top 0.254: R29.2 16.65,64.71 v16.85,64.86 | IC21.P129 68.75,57.31 64.2,61.81 53.25,61.81 51.55,63.51 47.05,63.51 46.6,64.01 46.57,63.98 J4.41
  Bottom 0.254: v16.85,64.86 19.25,64.86 | 19.25,64.86 19.25,64.51 | 19.25,64.86 21.85,64.86 23.95,66.96 23.95,71.11 23.6,71.46 23.6,75.16 24.7,76.26 24.7,79.36 26.7,81.36 34.65,81.36 37.4,78.61 37.4,71.26 43.3,65.36 45.15,65.36 46.55,63.96 J4.41 | D1.1 19.24,64.7 19.25,64.86
IRQS2  (via drill 0.3 pad 0.81)
  Top 0.254: R30.2 v16.85,67.01 | IC21.P128 69.25,57.86 64.55,62.51 53.55,62.51 51.8,64.26 48.2,64.26 47.25,65.21 45.85,65.21 44.6,66.46 44,66.46 44.01,66.47 J4.44
  Bottom 0.254: v16.85,67.01 17.7,67.01 18.3,67.61 18.75,67.61 19,67.91 | 19,67.91 20.1,67.91 22.9,70.71 22.9,75.46 24.05,76.61 24.05,79.71 26.35,82.01 35,82.01 38.05,78.96 38.05,71.66 43.2,66.51 44.05,66.56 J4.44 | D2.2 19.04,67.62 19,67.91
IRQS3  (via drill 0.3 pad 0.81)
  Top 0.254: R31.2 15.9,69.26 v17,70.36 | IC21.P127 69.75,58.31 64.75,63.26 53.85,63.26 52.1,65.01 48.7,65.01 47.2,66.51 J4.43
  Bottom 0.254: v17,70.36 17.85,70.36 18.3,69.91 19.25,69.91 | 19.25,69.91 20.25,69.91 22.2,71.86 22.2,75.76 23.4,76.96 23.4,80.06 26,82.66 35.35,82.66 38.7,79.31 38.7,72.31 43.2,67.81 45.2,67.81 46.55,66.46 J4.43 | D2.1 19.24,69.9 19.25,69.91
IRQS4  (via drill 0.3 pad 0.81)
  Top 0.254: v17,71.71 16.8,71.51 R32.2 | IC21.P125 70.75,58.31 65.05,63.96 54.2,63.96 52.4,65.76 49.15,65.76 47.1,67.81 45.8,67.81 44.6,69.01 44.05,69.01 J4.46
  Bottom 0.254: v17,71.71 17.2,71.51 18.65,71.51 18.9,71.76 18.9,72.46 | 18.9,72.46 20.15,72.46 21.5,73.81 21.5,76.06 22.75,77.31 22.75,80.36 25.7,83.36 35.65,83.36 39.35,79.66 39.35,72.81 43.15,69.01 43.95,69.01 J4.46 | D3.2 19.2,72.4 18.9,72.46
IRQS5  (via drill 0.3 pad 0.81)
  Top 0.254: R33.2 16.15,73.76 17,74.61 v17,74.76 | IC21.P124 71.25,58.86 63.6,66.46 49.75,66.46 47.15,69.06 J4.45
  Bottom 0.254: v17,74.76 17.15,74.61 19.25,74.61 | 19.25,74.61 20.2,74.61 20.85,75.26 20.85,76.41 22.1,77.66 22.1,80.71 25.45,84.06 35.95,84.06 40,80.01 40,73.46 43.1,70.36 45.25,70.36 J4.45 | D3.1 19.25,74.42 19.25,74.61
IRQS6  (via drill 0.3 pad 0.81)
  Top 0.254: R34.2 15.4,76.11 v17,76.11 | IC21.P123 71.75,59.36 63.9,67.16 50.3,67.16 47.1,70.36 45.9,70.36 44.65,71.61 44.04,71.6 J4.48
  Bottom 0.254: v17,76.11 17.25,75.86 19,75.86 19.25,76.11 19.25,76.86 | 19.25,76.86 20.1,76.86 21.45,78.21 21.45,80.96 25.2,84.76 36.25,84.76 40.65,80.36 40.65,74.06 43.1,71.61 43.95,71.61 44,71.66 44.01,71.65 J4.48 | D4.2 19.25,76.81 19.25,76.86
IRQS7  (via drill 0.3 pad 0.81)
  Top 0.254: R35.2 16.2,78.26 17,79.06 v17,79.36 | IC21.P122 72.25,59.81 64.2,67.86 50.7,67.86 46.94,71.6 J4.47
  Bottom 0.254: v17,79.36 17.35,79.01 19.35,79.01 | 19.35,79.01 20.2,79.01 20.8,79.61 20.8,81.26 25,85.46 36.6,85.46 41.3,80.76 41.3,74.76 43.25,72.81 44.7,72.81 45.9,71.61 J4.47 | D4.1 19.35,79.01
LCD_D0
  Top 0.254: IC13.3 142.5,74.31 142.7,74.11 142.7,62.81 146.75,58.76 148.95,58.76 150.2,59.96 150.18,59.98 J5.8
  Bottom 0.254: J5.8 151.73,59.98 153,58.71 154.85,58.71 156,57.56 156,56.51 155.98,56.49 R85.2
LCD_D1
  Top 0.254: IC13.4 142.95,74.96 143.4,74.51 143.4,63.51 146.9,60.01 147.6,60.01 J5.7
  Bottom 0.254: J5.7 148.84,58.76 151.25,58.76 152.25,57.76 153.05,57.76 153.5,57.31 153.5,56.41 153.52,56.41 R86.2
LCD_D2
  Top 0.254: IC13.5 143.3,75.61 144.1,74.81 144.1,64.11 146.85,61.36 149,61.36 J5.6
  Bottom 0.254: R87.2 154,62.51 153.99,62.52 J5.6
LCD_D3
  Top 0.254: IC13.6 143.6,76.26 144.8,75.06 144.8,64.66 146.9,62.56 147.55,62.56 147.6,62.51 J5.5
  Bottom 0.254: J5.5 148.83,61.31 151.9,61.31 153.2,60.01 154.07,60.01 R88.2
LCD_D4
  Top 0.254: IC13.7 143.9,76.91 145.5,75.31 145.5,65.26 146.9,63.86 148.95,63.86 J5.4
  Bottom 0.254: R89.2 154.1,65.05 154.1,65.06 J5.4
LCD_D5
  Top 0.254: IC13.8 144.25,77.56 146.2,75.61 146.2,65.96 147.1,65.06 J5.3
  Bottom 0.254: J5.3 148.97,66.41 151.95,66.41 153.05,67.51 154.02,67.51 R90.2
LCD_D6
  Top 0.254: IC13.9 144.6,78.21 146.9,75.91 146.9,70.86 J5.2
  Bottom 0.254: R91.2 152.57,70.01 J5.2
LCD_D7
  Top 0.254: IC13.10 144.95,78.86 147.6,76.21 147.6,72.21 151.55,68.26 151.55,67.01 150.95,66.41 148.75,66.41 147.62,67.54 J5.1
  Bottom 0.203: R92.2 147.52,70.38
  Bottom 0.254: R92.2 147.6,70.36 147.62,70.34 J5.1
LCD_E1  (via drill 0.3 pad 0.81)
  Top 0.254: IC14.4 91.93,42.44 v91.6,42.11
  Bottom 0.254: v91.6,42.11 92.67,41.01 92.67,35.56 98.4,29.86 107.6,29.86 113.55,35.81 121.8,35.81 124.55,38.56 141.85,38.56 144.35,41.06 144.35,41.76 147.55,44.96 148.7,44.96 152.1,48.36 152.1,55.56 150.22,57.44 J5.10
LCD_E2  (via drill 0.3 pad 0.81)
  Top 0.254: IC14.3 94.62,41.79 94.95,41.46 94.95,39.86 94.6,39.51 v94.55,39.51
  Bottom 0.254: v94.55,39.51 94.85,39.51 95.4,38.96 95.4,35.61 99.4,31.66 106.55,31.66 112.5,37.61 120.65,37.61 125.75,42.71 125.75,44.26 127.75,46.26 141.9,46.26 146.35,50.71 146.35,56.16 J5.9
LCD_RS  (via drill 0.3 pad 0.81)
  Top 0.254: v91.6,43.26 91.75,43.26 92.23,43.74 IC14.6
  Bottom 0.254: v91.6,43.26 92,43.26 93.33,41.91 93.33,35.91 98.75,30.46 107.25,30.46 113.2,36.41 121.4,36.41 126.05,41.06 142.4,41.06 147.1,45.76 148.4,45.76 151.4,48.76 151.4,53.71 150.2,54.91 150.19,54.9 J5.12
LCD_RW  (via drill 0.3 pad 0.81)
  Top 0.254: IC14.5 95.07,43.09 95.6,42.56 95.6,39.11 94.75,38.26 v94.5,38.26
  Bottom 0.254: v94.5,38.26 94.5,35.61 99.1,31.06 106.9,31.06 112.85,37.01 121,37.01 127.6,43.61 143.65,43.61 148.9,48.86 148.9,53.71 147.62,54.88 J5.11
N$1  (via drill 0.3 pad 0.81)
  Top 0.254: SW2.1 119.87,95.61 v121.95,95.61
  Bottom 0.254: v121.95,95.61 121.95,96.46 | 121.95,96.46 121.95,97.56 122.55,98.16 131.7,98.16 141.3,88.46 141.3,86.06 141.31,86.05 J3.2 | R8.2 121.96,96.47 121.95,96.46
N$2  (via drill 0.3 pad 0.81)
  Top 0.254: IC21.P72 78.75,31.06 79.05,30.76 80.1,30.76 80.4,30.46 v80.45,30.46
  Route15 0.254: v57.05,8.66 57.02,8.66 59.48,11.11 v59.48,16.03
  Bottom 0.254: v80.45,30.46 80.3,30.61 78.35,30.61 78.2,30.46 76.55,30.46 75.5,29.41 73.7,29.41 73.3,29.81 71.5,29.81 68.65,26.96 59.85,26.96 59.4,26.51 59.4,19.91 | 59.4,19.91 IC1.3 | 59.4,19.91 59.4,19.08 60.17,18.31 60.17,16.73 v59.48,16.03 | v57.05,8.66 57.02,8.63 57.35,8.31 R155.1
N$3  (via drill 0.3 pad 0.81)
  Top 0.254: IC21.P71 78.25,30.56 79.05,29.76 v79.4,29.76
  Bottom 0.254: v79.4,29.76 76.8,29.76 75.8,28.76 73.15,28.76 68.4,24.01 68.4,23.01 67.15,21.76 65.95,21.76 | 63.94,19.92 IC1.10 63.95,19.91 63.94,19.92 | 63.94,19.92 63.94,19.9 63.9,19.86 | 65.95,21.76 65.95,22.81 R6.2 | 63.94,19.92 63.94,21.26 64.45,21.76 65.95,21.76
N$4  (via drill 0.3 pad 0.81)
  Top 0.254: IC21.P111 77.75,56.01 v78.15,56.41
  Bottom 0.254: R1.1 77.66,56.9 v78.15,56.41
N$5  (via drill 0.3 pad 0.81)
  Top 0.254: IC21.P110 78.25,55.26 v79.4,56.41
  Bottom 0.254: R2.1 77.41,58.95 79.4,56.96 79.4,56.46 79.35,56.41 v79.4,56.41
N$6
  Bottom 0.254: R7.1 127.99,96.47 R8.1 125.63,93.68 125.65,93.66 125.63,93.64 IC2.3 125.61,93.7 125.48,93.83 R10.2 121.12,93.83 120.35,93.81 120.35,95.16 119.5,96.01 C1.1
N$7
  Top 0.406: C7.1 66.08,87.08 66.05,87.11 66.09,87.15 R11.2 64.02,87.18 63.97,87.13 R12.1 63.9,87.16 63.79,87.05 IC3.1
N$8
  Bottom 0.254: R3.2 60.04,11.75 60.05,11.76 60.04,11.77 IC1.17
N$9  (via drill 0.3 pad 0.81)
  Top 0.254: IC21.P144 61.25,54.71 60.4,55.56 v60.4,55.76
  Bottom 0.254: v60.4,55.76 59.75,55.76 58.7,54.71 58.7,37.01 58,36.31 58,23.86 57.45,23.26 56.05,23.26 55.7,23.61 53.95,23.61 52.8,22.46 52.8,12.91 54.3,11.41 57.8,11.41 58.12,11.73 R3.1
N$10  (via drill 0.3 pad 0.81)
  Top 0.254: IC21.P143 61.75,55.71 v61.7,55.76 | v63.5,24.31 60.25,24.31 59.45,25.11 57.2,25.11 v57.15,25.16
  Bottom 0.254: IC1.7 61.99,19.95 62,19.96 62,21.41 61.59,21.82 R4.2 | R4.2 61.6,22.61 61.59,23.05 R4.2 | v61.7,55.76 61.7,56.16 61.2,56.66 59.75,56.66 58.1,55.01 58.1,37.31 57.4,36.61 57.4,25.41 v57.15,25.16 57.15,24.61 56.85,24.31 54.7,24.31 54.38,24.63 D22.1 | v63.5,24.31 63.5,23.46 62.7,22.66 R4.2 | D22.2 D22.1 | D22.1 54.45,25.51 54.5,25.46
N$11
  Top 0.254: L1.1 84.3,73.51 84.6,73.26 | 84.2,69.01 84.55,69.01
  Top 0.305: 84.55,69.01 IC5.8 | IC5.9 83.9,68.71 83.95,68.76
  Top 0.406: 83.95,68.76 84.2,69.01
  Top 1.016: 84.55,69.01 85.1,69.56 85.1,72.76 84.6,73.26
  pour Top (isolate 0.305, no thermals): 83.85,67.91 86.05,67.91 86.05,75.41 82.65,75.41 82.65,71.21 83.85,71.21
N$12  (via drill 0.3 pad 0.81)
  Top 0.254: v116.95,86.81 116.4,87.36 R9.2 | IC23.95 109.03,63.13 107.8,64.36 107.8,66.41 v107.95,66.56
  Route15 0.254: v116.95,86.81 116.35,86.21 116.35,70.46 115.05,69.16 110.55,69.16 v107.95,66.56
N$13  (via drill 0.3 pad 0.81)
  Top 0.254: v81.88,60.53 82.15,60.53 82.6,60.98 IC5.4
  Route15 0.254: v79.25,66.71 81.88,64.11 v81.88,60.53
  Bottom 0.254: v79.25,66.71 C8.1
N$15  (via drill 0.3 pad 0.81)
  Top 0.406: C6.+ 52.72,80.26 52.7,79.41 | R13.2 54.33,80.89 53.75,80.31 50.65,80.31 50.7,80.25
  Top 0.813: C6.+ 50.7,80.25 50.7,80.26 50.68,80.24 R16.1 | v52.7,78.46 v52.7,79.36 52.7,79.41
  Bottom 0.813: v52.7,78.46 v52.7,79.36 52.6,79.46 52.6,81.03 IC4.4 52.65,81.06 52.65,87.23 IC4.2
  other vias: 51.25,84.41 52.65,84.41 52.65,82.91 51.25,82.91 51.95,83.66
  pour Bottom (isolate 0.305, no thermals): 37.05,90.41 37.1,78.81 41.75,74.06 57,74.16 56.95,90.41
  pour Route15: 46.7,84.31 46.7,80.86 47.55,80.86 48.75,82.06 59.95,82.06 60.4,82.51 64,82.51 64,83.66 60.65,87.01 49.4,87.01
  pour Route2: 50.2,89.16 64.7,89.16 64.7,67.21 56.35,67.21 50.2,73.36
  pour Top (no thermals): 43.4,86.96 43.4,74.61 56.3,74.61 56.3,86.96
N$16  (via drill 0.3 pad 0.81)
  Top 0.254: IC6.22 19.77,25.73 19.4,25.36 19.4,18.51 20.05,17.86 21.6,17.86 21.8,18.06 v21.75,18.06
  Bottom 0.254: R18.1 21.77,18.08 v21.75,18.06
N$17
  Bottom 0.254: 18.15,91.36 C51.1 R40.2
N$18
  Bottom 0.254: R37.1 13.69,91.32 13.65,91.36 R39.1 D7.3
N$19
  Bottom 0.254: C104.1 58.91,96.55 59.25,96.21 | D25.3 60.75,96.21 60.6,96.06 | 60.6,94.26 60.59,94.27 J2.1
  Bottom 0.61: 60.75,96.21 59.25,96.21 | 60.6,96.06 60.6,94.26
N$20  (via drill 0.3 pad 0.81)
  Top 0.254: v34.67,94.03 34.67,94.01 IC11.6
  Bottom 0.203: 34.7,94.06 v34.67,94.03
  Bottom 0.254: R53.2 34.66,93.85 34.7,94.06
N$21  (via drill 0.3 pad 0.76)
  Route2 0.254: v26.25,53.21 26.15,53.31 26.15,60.46 27.15,61.46 v27.4,61.46
  Bottom 0.203: IC12.26 25.38,64.64 25.4,64.51
  Bottom 0.254: 25.4,64.51 25.4,62.66 26.6,61.46 v27.4,61.46 | v26.25,53.21 22.6,56.86 16.25,56.86 14.93,55.53 14.93,42.88 17.75,40.06 20.65,40.06 22.1,38.61 27.9,38.61 28.95,37.56 28.95,36.46 29.75,35.66 30.3,35.66 30.93,35.03 R54.2
N$22  (via drill 0.3 pad 0.76)
  Top 0.254: IC10.6 34.67,78.78 v34.9,78.56
  Bottom 0.254: 35.13,76.74 35.15,76.76 | R28.2 35.13,76.74 | 35.13,76.74 35.15,76.71 | 35.13,76.74 35.13,78.33 v34.9,78.56
N$23
  Top 0.254: 152.35,52.36 J5.14 | 152.35,52.36 152.35,72.46 143.1,81.71 132.6,81.71 128.55,85.76 111.9,85.76 110.95,86.71 R67.2 | 152.35,52.36 152.35,48.91 150.95,47.51 149.85,47.51 C74.1
N$24  (via drill 0.3 pad 0.81)
  Top 0.254: R55.2 113.48,26.43 113.52,26.43 113.55,26.46 114.45,26.46 115.1,27.11 v115.5,27.11
  Bottom 0.254: v115.5,27.11 115.3,27.11 114.59,26.4 IC15.19
N$25
  Bottom 0.254: C75.1 115.08,34.39 115.1,34.36 115.2,34.16
  Bottom 0.305: IC15.27 114.8,31.6 115.2,32.01 115.2,34.16
N$26  (via drill 0.3 pad 0.81)
  Top 0.254: C76.1 117.46,28.85 117.45,28.86 117.5,28.91 v117.5,30.11
  Top 0.305: D14.3 109.75,33.56 109.9,33.71 114.55,33.71 117.5,30.76 v117.5,30.11
  Bottom 0.254: IC15.3 118.34,30.95 v117.5,30.11
N$27
  Bottom 0.254: 110.92,26.24 111.3,26.26 | R56.2 110.92,26.24 | IC15.18 111.41,25.75 110.92,26.24
N$28  (via drill 0.3 pad 0.81)
  Top 0.254: C77.2 113.35,32.06 113.15,32.26 112.1,32.26 v111.8,32.56
  Bottom 0.254: IC15.28 112.11,32.25 v111.8,32.56
N$29  (via drill 0.3 pad 0.81)
  Top 0.254: C77.1 112.95,29.86 111.85,29.86 v111.7,29.71
  Bottom 0.254: v111.7,29.71 111.8,29.71 111.86,29.65 IC15.24
N$30
  Bottom 0.254: C78.2 122.7,32.76 122.25,32.3 120.7,32.31 120.64,32.25 IC15.1
N$31
  Bottom 0.254: IC15.2 121.25,31.61 121.31,31.55 124.14,31.55 124.4,31.81 124.4,32.56 124.35,32.76 C78.1
N$32  (via drill 0.3 pad 0.81)
  Top 0.254: v115.5,25.86 115.85,25.86 117,27.01 117.9,27.01 122.05,22.86 122.05,22.51 122.04,22.5 R57.2
  Bottom 0.254: IC15.17 114.64,25.1 115.4,25.86 v115.5,25.86
N$33
  Bottom 0.254: R58.2 111.38,24.29 111.55,24.45 IC15.16
N$34  (via drill 0.3 pad 0.81)
  Top 0.254: v115.55,24.46 115.67,24.39 R59.2
  Bottom 0.254: IC15.15 114.89,23.8 v115.55,24.46
N$35
  Top 0.254: R159.1 16.23,16.43 16.05,16.61 16.05,18.01 16.65,18.61 16.68,18.63 16.68,25.78 16.1,26.36 14.8,26.36 IC6.2
N$36
  Top 0.254: D9.3 104.08,25.34 105.25,26.51 107.8,26.51 107.96,26.67 D10.3 107.96,26.92 107.95,26.91 108,26.86 108.75,26.86 109.25,26.36 109.25,24.46 111.15,22.56 D8.3 114.29,21.87 114.9,21.26 117.3,21.26 117.55,21.01 122.25,21.01 122.95,20.31 122.95,19.46 R60.1
N$37
  Bottom 0.254: T2.1 135.94,83.85 136.35,84.26 136.35,86.71 137.75,88.11 137.75,90.76 137.15,91.36 131.55,91.36 131.05,90.86 131.05,90.01 131,89.96 R70.1
N$38
  Bottom 0.254: C80.1 91.34,11.7 90.75,11.11 89.6,11.11 89.59,11.09 IC16.27
N$39  (via drill 0.3 pad 0.81)
  Top 0.254: D15.3 106.41,31.25 106.15,31.51 94.4,31.51 94.05,31.16 94.05,25.31 94.55,24.81 94.55,23.21 93.3,21.96 93.3,14.71 v93.9,14.11
  Bottom 0.254: C81.1 92.18,15.83 v93.9,14.11 93.9,11.91 95.35,10.46 96.4,10.46 96.41,10.44 IC16.3
N$40
  Bottom 0.254: C82.2 86.98,11.73 87,11.71 87.03,11.74 IC16.28
N$41
  Bottom 0.254: C82.1 87.25,10.11 87.52,9.84 87.52,9.34 87.7,9.16 89.55,9.16 89.56,9.14 IC16.24
N$42
  Bottom 0.254: IC16.1 97.78,11.74 98.25,12.21 99.15,12.21 99.12,12.24 C83.2
N$43
  Bottom 0.254: IC16.2 100.73,11.09 100.95,11.31 100.95,12.16 101,12.21 C83.1
N$44
  Bottom 0.254: IC16.19 80.77,5.89 80.5,6.16 80.5,6.91 80.47,6.94 R61.2
N$45
  Bottom 0.254: IC16.18 78.86,5.24 78,6.11 78,6.91 77.98,6.93 R62.2
N$46
  Bottom 0.254: IC16.17 78.06,4.59 76.6,6.06 75.65,6.06 75.45,6.26 75.45,6.91 75.47,6.93 R63.2
N$47
  Bottom 0.254: IC16.16 77.61,3.94 76.2,5.36 73.6,5.36 73,5.96 73,6.91 73.05,6.96 73.03,6.98 R64.2
N$48
  Bottom 0.254: IC16.15 77.22,3.29 76.5,4.01 75,4.01 74.95,3.96 R65.2
N$49
  Bottom 0.254: D11.3 68.41,7.3 68.35,7.46 D13.3 68.4,10.01 68.38,10.01 | D12.3 76.7,13.26 73.1,13.26 69.9,10.06 68.4,10.06 R66.1 68.38,10.01 | 68.38,10.01 68.35,10.01
N$50
  Bottom 0.254: T3.1 128,83.26 128,83.76 128.55,84.31 128.55,90.86 128.15,91.26 123.45,91.26 123.05,90.86 123.05,89.91 R71.1
N$51  (via drill 0.3 pad 0.81)
  Top 0.254: LED1.A 106.96,95 106.84,95 106.8,94.96 106.1,94.96 105.1,96.01 v105.1,98.01
  Route2 0.254: v9.35,91.46 8.1,92.66 8.1,96.26 10.35,98.51 104.55,98.51 105.1,97.96 v105.1,98.01 105.1,98.06
  Bottom 0.254: v9.35,91.46 10.7,91.46 12.1,90.06 12.1,86.26 12.95,85.41 12.95,84.11 R19.2
N$52  (via drill 0.3 pad 0.81)
  Top 0.254: LED2.A 111.54,92.2 109.35,90.01 106.1,90.01 104.45,91.66 82.25,91.66 81.85,91.26 v81.8,91.26
  Bottom 0.254: v81.8,91.26 81.8,91.31 81.59,91.1 R74.1
N$53  (via drill 0.3 pad 0.81)
  Top 0.254: v102.35,94.61 102.4,94.61 102.3,94.71 SW1.9
  Bottom 0.254: D16.2 102.03,94.29 v102.35,94.61
N$54  (via drill 0.3 pad 0.81)
  Top 0.254: SW1.10 v99.76,94.62 v99.75,94.61
  Bottom 0.254: v99.75,94.61 99.7,94.61 100.13,94.18 D16.1
N$55  (via drill 0.3 pad 0.81)
  Top 0.254: v97.25,94.61 97.25,94.66 97.22,94.69 SW1.11
  Bottom 0.254: 97.3,94.66 v97.25,94.61 96.93,94.29 D17.2
N$56  (via drill 0.3 pad 0.81)
  Top 0.254: v94.65,94.61 94.65,94.66 94.68,94.69 SW1.12
  Bottom 0.254: v94.65,94.61 94.6,94.61 95.03,94.18 D17.1
N$57  (via drill 0.3 pad 0.81)
  Top 0.254: SW1.13 v92.14,94.62 v92.15,94.61
  Bottom 0.254: v92.15,94.61 92.15,94.56 91.83,94.24 D18.2
N$58  (via drill 0.3 pad 0.81)
  Top 0.254: v89.6,94.61 SW1.14
  Bottom 0.254: D18.1 89.93,94.28 v89.6,94.61
N$59  (via drill 0.3 pad 0.81)
  Top 0.254: v87.05,94.61 87,94.61 87.06,94.67 SW1.15
  Bottom 0.254: D19.2 86.78,94.34 v87.05,94.61
N$60  (via drill 0.3 pad 0.81)
  Top 0.254: v84.5,94.61 84.45,94.61 84.52,94.68 SW1.16
  Bottom 0.254: D19.1 84.88,94.23 v84.5,94.61
N$61  (via drill 0.3 pad 0.81)
  Top 0.254: IC13.23 136.25,73.66 v136.5,73.41 136.55,73.41 136.15,73.01 IC13.24
  Bottom 0.406: C70.1 137.01,68.02 137,68.01 136.94,68.07 R82.1 136.94,72.1 136.94,72.97 v136.5,73.41
N$62  (via drill 0.3 pad 0.81)
  Top 0.254: IC13.1 141.4,73.01 141.5,72.96 v141.5,72.11
  Bottom 0.406: C69.1 141.07,71.68 v141.5,72.11 141.74,71.87 R83.1
N$63  (via drill 0.3 pad 0.81)
  Top 0.406: IC3.2 61.48,85.64 61.95,86.11 61.95,87.06 R12.2
  Top 0.61: 53.87,78.28 53.9,78.21 53.9,78.26 v53.9,78.31 v53.9,79.21
  Top 0.813: v52.35,92.61 v52.35,91.56 52.35,89.91 56.05,86.21 56.05,78.91 55.45,78.31 v53.9,78.31 | v61.5,79.81 v62.5,79.81 v61.5,79.81 | IC3.2 61.48,80.08 61.55,80.01 61.53,80.09 v61.5,79.81 | IC3.4 61.48,78.29 61.5,78.31 v61.5,79.81
  Top 1.016: R15.1 60.39,77.7 60.85,78.16 61.45,78.16 61.48,78.13 IC3.4 | IC3.4 61.48,78.14 61.85,78.51 66.95,78.51 67.4,78.06 67.4,76.16 67.67,76.14 C2.+ | IC3.4 61.48,78.24 61.5,78.26 61.48,78.28
  Route15 0.813: v53.9,78.31 v53.9,79.21 60.9,79.21 v61.5,79.81 v62.5,79.81
  Bottom 0.406: 54.9,87.21 54.93,87.24 IC4.3
  Bottom 0.813: 54.9,87.21 54.9,88.66 53.59,89.97 C4.1 52.35,89.86 v52.35,91.56 v52.35,92.61
  other vias: 61.5,81.11 62.5,81.11
  pour Top (isolate 0.305): 69.5,90.36 69.5,82.71 65.6,82.71 65.6,84.11 63.9,84.11 63.9,85.96 57.05,85.96 57.05,73.71 57.95,72.81 70.65,72.81 70.65,77.76 78.4,77.76 79.15,78.51 79.15,90.36
  pour Route15: 46.7,80.21 46.7,77.11 83.3,77.11 83.3,81.96 60.65,81.96 60.15,81.46 48.95,81.46 47.7,80.21
  pour Bottom: 64.85,89.06 64.85,65.21 60.55,65.21 60.55,89.06
N$64  (via drill 0.3 pad 0.81)
  Top 0.254: v91.45,40.51 91.57,40.54
  Top 0.406: 91.57,40.54 91.67,40.49 92.98,40.49 | 92.98,40.49 IC14.1 | C93.1 92.84,40.35 92.98,40.49
  Bottom 0.254: R84.1 90.94,39.07
  Bottom 0.406: 90.95,40.51 90.95,39.36 90.94,39.45 90.94,39.07 | 90.95,40.51 90.5,40.51 90.28,40.73 90.28,41.33 90,41.61 C71.1 | 90.95,40.51 91.35,40.51 91.45,40.61 v91.45,40.51
N$65
  Top 0.254: JP1.1 56.43,22.79 54.85,21.21 54.85,20.76 53.74,19.65 Q2.3
N$66
  Top 0.254: Q1.3 61.75,19.71 61.59,20.3 61.05,20.38 61.04,21.92 JP1.3
N$67  (via drill 0.3 pad 0.81)
  Top 0.254: IC18.13 100.39,19.11 100.4,19.11 v100.4,17.21
  Bottom 0.254: R111.2 100.42,15.86 100.4,15.86 v100.4,17.21
N$68
  Top 0.254: R9.1 116.4,93.31 116,93.71 LED11.A
N$69
  Top 0.254: R113.2 80.88,70.33 80.85,70.26 80.65,70.23 80.65,69.01 | IC5.14 80.65,69.01 | R112.1 80.64,69.02 80.65,69.01
N$70
  Top 0.254: R103.1 82.49,6.87 84.3,5.06 LED3.A
N$71
  Top 0.254: R104.1 80.04,5.42 80.2,5.26 81.75,5.26 LED4.A
N$72
  Top 0.254: R105.1 76.06,5.95 76.95,5.06 77.95,5.06 77.96,5.07 LED5.A
N$73
  Top 0.203: LED6.A 73.96,5.07 73.9,5.01
  Top 0.254: LED6.A 74.01,5.2 73.99,5.22 R106.1
N$74
  Top 0.254: R107.1 66.99,7.47 67.01,7.45 LED7.A
N$75
  Top 0.254: R108.1 62.99,7.6 63,7.61 63.01,7.6 LED8.A
N$76
  Top 0.254: R109.1 58.99,7.52 59.01,7.5 LED9.A
N$77
  Top 0.254: R110.1 54.99,7.52 55.01,7.5 LED10.A
N$78
  Top 0.254: IC20.7 85.14,11.99 82.5,9.36 82.5,8.86 82.49,8.85 R103.2
N$79
  Top 0.254: IC20.6 83.86,11.92 82.45,10.51 82,10.51 80.1,8.61 80.1,7.46 80.04,7.4 R104.2
N$80
  Top 0.254: IC20.5 82.59,11.8 82,11.21 81.7,11.21 79.75,9.26 78.95,9.26 77.95,8.26 77.95,7.41 77.96,7.4 R105.2
N$81
  Top 0.254: IC20.4 81.33,11.83 79.45,9.96 74.35,9.96 74.05,9.66 74.05,8.86 74.03,8.84 R106.2
N$82
  Top 0.254: IC20.3 80.06,11.66 79,10.61 67.35,10.61 67,10.26 67,9.61 66.99,9.6 R107.2
N$83
  Top 0.254: 63,9.51 62.99,9.5 R108.2 63.03,9.48 63.05,9.46 63.05,10.41 63.9,11.26 78.35,11.26 78.78,11.69 IC20.2
N$84
  Top 0.254: 59.05,9.51 R109.2 58.99,9.5 59,9.51 59,10.41 60.5,11.91 77.4,11.91 77.5,12.01 77.5,12.11 77.52,12.12 IC20.1
N$85
  Top 0.254: 55,9.61 54.99,9.6 R110.2 54.99,9.5 55.05,9.56 55.05,10.46 57.15,12.56 74.5,12.56 78.78,16.84 IC20.15
N$86
  Bottom 0.254: 155.05,39.91 158.8,39.91 158.8,19.41 155.05,19.41 155.05,39.91
N$87
  Route15 0.254: 155.05,19.41 155.05,39.91 158.8,39.91 158.8,19.41 155.05,19.41
N$88
  Route2 0.254: 155.05,19.46 155.05,39.96 158.8,39.91 158.8,19.41 155.05,19.46
N$89
  Top 0.254: 155.05,19.41 155.05,39.91 158.8,39.91 158.8,19.41 155.05,19.41
N$90
  Top 1.27: F1.2 26.3,6.04 26.3,6.06 20.98,6.06 J11.2
N$91  (via drill 0.3 pad 0.81)
  Top 0.254: IC23.10 101.95,55.16 v101.5,54.71
  Route15 0.203: v101.5,54.71 100.85,54.71 100.45,55.11 98.05,55.11 93.9,59.26 93.9,64.11 82.25,75.71 66.5,75.71 65.25,74.46 63.05,74.46 61.85,75.66 50.15,75.66 47.35,72.86 43.25,72.86 41.3,74.81 25.55,74.81 18.7,67.96 15.95,67.96 15.15,67.16 15.15,37.81 16.3,36.66 v17.7,36.66
  Bottom 0.254: v17.7,36.66 18.3,36.71 18.82,36.14 R146.2
N$93
  Route2 0.203: 76,73.76 71.25,78.51 71.25,89.21 77,89.21 87,79.21 87,59.66 75.75,59.66 71.25,64.16 71.25,68.81 76,68.81
N$101
  Bottom 0.254: IC24.2 120.56,64.31 121.05,64.81 121.05,66.96 121.75,67.66 122.45,67.66 Q3.1
N$102
  Bottom 0.254: IC24.1 118.84,66.69 121.35,69.21 124.6,69.21 125.12,68.68 125.12,67.68 | 125.12,67.68 125.12,67.69 Q3.2 | 125.12,67.68 125.12,67.61
N$103
  Bottom 0.254: D23.3 67.22,60.34 67.45,60.11 67.45,59.61 67.75,59.31 68.55,59.31 68.62,59.24 D24.1
N_ACK
  Top 0.254: IC23.89 112.03,67.28 103.7,75.61 103.7,77.51 J15.19
  Bottom 0.254: J15.19 102.38,78.84 102.44,78.9 R142.1
N_AUTOFD
  Top 0.254: IC23.71 122.2,57.66 122.95,58.41 122.95,61.71 125.25,64.01 125.25,76.26 J15.2
N_BUSENA  (via drill 0.3 pad 0.81)
  Top 0.254: IC21.P40 62.75,30.86 62.45,30.56 59.25,30.56 v59,30.81
  Route15 0.254: v59,30.81 58.95,30.81 57.55,32.21 37.2,32.21 35.9,30.91 35.9,24.36 30.75,19.21 30.75,18.66 v30.7,18.61
  Bottom 0.254: v30.7,18.61 30.65,18.61 30.12,18.08 R18.2
N_CS10
  Top 0.254: IC23.67 123.05,55.66 124.75,57.36 124.75,60.71 127.9,63.86 129.8,63.86 130.95,62.71 J12.37
N_CS11
  Top 0.254: IC23.66 123.4,55.16 125.35,57.11 125.35,60.11 127.9,62.66 128.4,62.66 J12.38
N_CS20  (via drill 0.3 pad 0.81)
  Top 0.254: IC23.59 125.1,51.66 127.25,53.81 132.85,53.81 v133.7,52.91
  Bottom 0.254: v133.7,52.91 134.85,51.76 136.45,51.76 137.15,52.46 137.15,60.76 137.85,61.46 139.7,61.46 J13.37 | J13.37 141,62.76 | J13.37
N_CS21  (via drill 0.3 pad 0.81)
  Top 0.254: IC23.58 | IC23.58 125.5,51.16 125.65,51.31 134.9,51.31 135.85,52.26 v135.85,52.91
  Bottom 0.254: J13.38 137.03,62.74 136.45,62.16 136.45,53.56 v135.85,52.91
N_CSRAM1  (via drill 0.3 pad 0.76, 0.3 pad 0.81)
  Top 0.254: IC21.P46 65.75,30.96 62.95,28.16 60.9,28.16 v60.5,28.56
  Route2 0.203: v60.5,28.56 60.45,28.51
  Route2 0.254: v35.15,73.06 37.3,73.06 42.5,67.86 48.65,67.86 55.25,61.26 55.25,36.36 60.45,31.16 60.45,28.51
  Route15 0.254: v60.5,28.56 58.4,28.56 56.8,30.16 50.85,30.16 47.9,27.16 43.1,27.16 v40.65,29.61
  Bottom 0.203: R28.1 34.9,74.66
  Bottom 0.254: v35.15,73.06 R28.1
N_CSRAM2  (via drill 0.3 pad 0.76, 0.3 pad 0.81)
  Top 0.152: 31.5,84.51 31.5,87.31 | 30.25,82.56 30.25,79.56 29.8,79.11
  Top 0.203: 31.5,87.31 v32.05,87.86 | 30.25,82.56 31.5,84.51 | 29.8,79.11 29.8,78.26 30.7,77.36 30.7,77.11 32.1,75.71 v32.1,73.86
  Top 0.254: IC21.P47 66.25,30.66 65,29.41 65,28.61 v64.95,28.56
  Route2 0.254: v32.1,73.86 32.65,74.41 38.55,74.41 42.75,70.21 47.5,70.21 56.15,61.56 56.15,36.61 60.5,32.26 61.25,32.26 v64.95,28.56
  Route15 0.254: v64.95,28.56 63.15,28.56 62.3,27.71 58.15,27.71 56.5,29.36 52.05,29.36 47.35,24.66 42.45,24.66 40.75,26.41 40.75,27.61 v39.7,28.61
  Bottom 0.254: R53.1 34.66,89.25 33.25,87.86 v32.05,87.86
N_CSROM  (via drill 0.3 pad 0.76, 0.3 pad 0.81)
  Top 0.254: IC21.P44 64.75,30.96 62.85,29.06 v61.85,29.06 | v30.95,30.51 36.8,30.51 v36.85,30.56
  Route15 0.254: v61.85,29.06 61.2,29.71 58.4,29.71 57.1,31.01 49.35,31.01 48.05,29.71 43.1,29.71 41.4,31.41 37.7,31.41 v36.85,30.56
  Bottom 0.254: R54.1 30.92,30.83 v30.95,30.51
N_CTS0  (via drill 0.3 pad 0.81)
  Top 0.254: v108.5,22.61 109.5,21.61 D8.2 | v77.3,22.06 77.3,22.46 73,26.76 73,29.81 72.25,30.56 IC21.P59
  Bottom 0.254: R58.1 109.15,23.81 109.13,23.79 109.13,23.24 v108.5,22.61 107.5,21.61 90.85,21.61 87.82,24.64 86.27,24.64 84.52,22.91 78.1,22.91 77.3,22.11 v77.3,22.06
N_CTS1  (via drill 0.3 pad 0.81)
  Top 0.254: v93.15,4.51 93.15,10.41 90.5,13.06 90.5,27.26 82,35.76 IC21.P76
  Bottom 0.203: 70.46,6.12 69.5,5.16 69.5,3.41
  Bottom 0.254: v93.15,4.51 93.15,3.81 91.3,1.96 70.95,1.96 69.5,3.41 | R64.1 72.95,9.01 72.95,10.06 72.7,10.31 71.8,10.31 70.7,9.21 70.7,6.21 70.61,6.12 | 70.61,6.12 70.6,6.11 | 70.61,6.12 D11.1 | 70.46,6.12 70.61,6.12
N_DASP0
  Top 0.254: IC23.68 120.6,56.16 120.65,56.16 122.7,56.16 124.15,57.61 124.15,61.01 127.1,63.96 127.1,65.81 127.75,66.46 129.7,66.46 J12.39 132.43,65.23 132.46,65.2 R122.1
N_DASP1  (via drill 0.3 pad 0.81)
  Top 0.254: IC23.61 124.35,52.66 128,56.31 v135.5,56.31
  Bottom 0.254: v135.5,56.31 135.5,62.66 136.85,64.01 139.7,64.01 J13.39 141,65.31 141.27,65.04 R121.1
N_DCD0  (via drill 0.3 pad 0.81)
  Top 0.254: R55.1 111.67,26.23 111.7,26.26 110.8,26.26 110,27.06 v110,28.01 110,28.51 109.57,28.94 109.07,28.94 109,29.01 D10.1 | v74.3,22.21 74.3,22.61 70.75,26.16 IC21.P56
  Bottom 0.254: v110,28.01 108.2,28.01 103.25,23.06 91.45,23.06 88.5,26.01 85.65,26.01 83.75,24.11 76.1,24.11 74.3,22.31 v74.3,22.21
N_DCD1  (via drill 0.3 pad 0.81)
  Top 0.254: 87.35,5.86 86.9,6.31 85.15,6.31 v84.75,6.71 | 87.35,5.86 89.65,5.86 90.45,6.66 90.45,11.21 89.1,12.56 89.1,20.66 87.6,22.16 85.7,22.16 77.75,30.11 IC21.P70 | 87.35,5.86 87.35,4.36 87,4.01 69.6,4.01 68.6,3.01 v68.6,2.96
  Bottom 0.254: R61.1 81.77,8.94 82,8.71 82,7.66 82.95,6.71 v84.75,6.71 | v68.6,2.96 68.25,2.96 66.2,5.01 D13.1
N_DIOR
  Top 0.254: J12.25 130.9,47.46 130.9,46.26 130.85,46.26 | 130.85,46.26 127.65,46.26 124.25,49.66 IC23.55 | J13.25 139.73,46.26 130.85,46.26
N_DIOW
  Top 0.254: J12.23 130.87,44.86 130.95,44.86 130.95,43.71 130.9,43.71 | 130.9,43.71 127.7,43.71 127.05,44.36 127.05,46.01 123.9,49.16 IC23.54 | IC23.54 | J13.23 139.72,43.71 130.9,43.71
N_DMACK
  Top 0.254: J12.29 131.49,51.96 134.3,51.96 134.75,52.41 134.75,53.41 135.2,53.86 139.75,53.86 141,52.61 J13.29
  Bottom 0.254: R124.1 143.32,52.56 140.99,52.56 J13.29
N_DRESET
  Top 0.254: 130.9,15.66 127.35,15.66 125.1,17.91 125.1,22.51 120.2,27.41 120.2,30.41 114.45,36.16 113.3,36.16 107.05,42.41 107.05,45.66 IC23.27 | J13.1 140.99,17.02 141,17.01 139.65,15.66 130.9,15.66 | J12.1 130.92,16.99 130.9,17.01 130.9,15.66
N_DSR0  (via drill 0.3 pad 0.81)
